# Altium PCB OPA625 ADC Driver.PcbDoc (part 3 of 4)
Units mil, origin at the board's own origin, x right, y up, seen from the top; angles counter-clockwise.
Board outline 4590 x 3930 mil, 4 copper layers (Layer 1 - Top Layer, Layer 2 - GND, Layer 3 - PWR, Layer 4 - Bottom Layer), stack 59.034 mil thick; 428 components, 236 nets, 1203 pads, 546 vias.
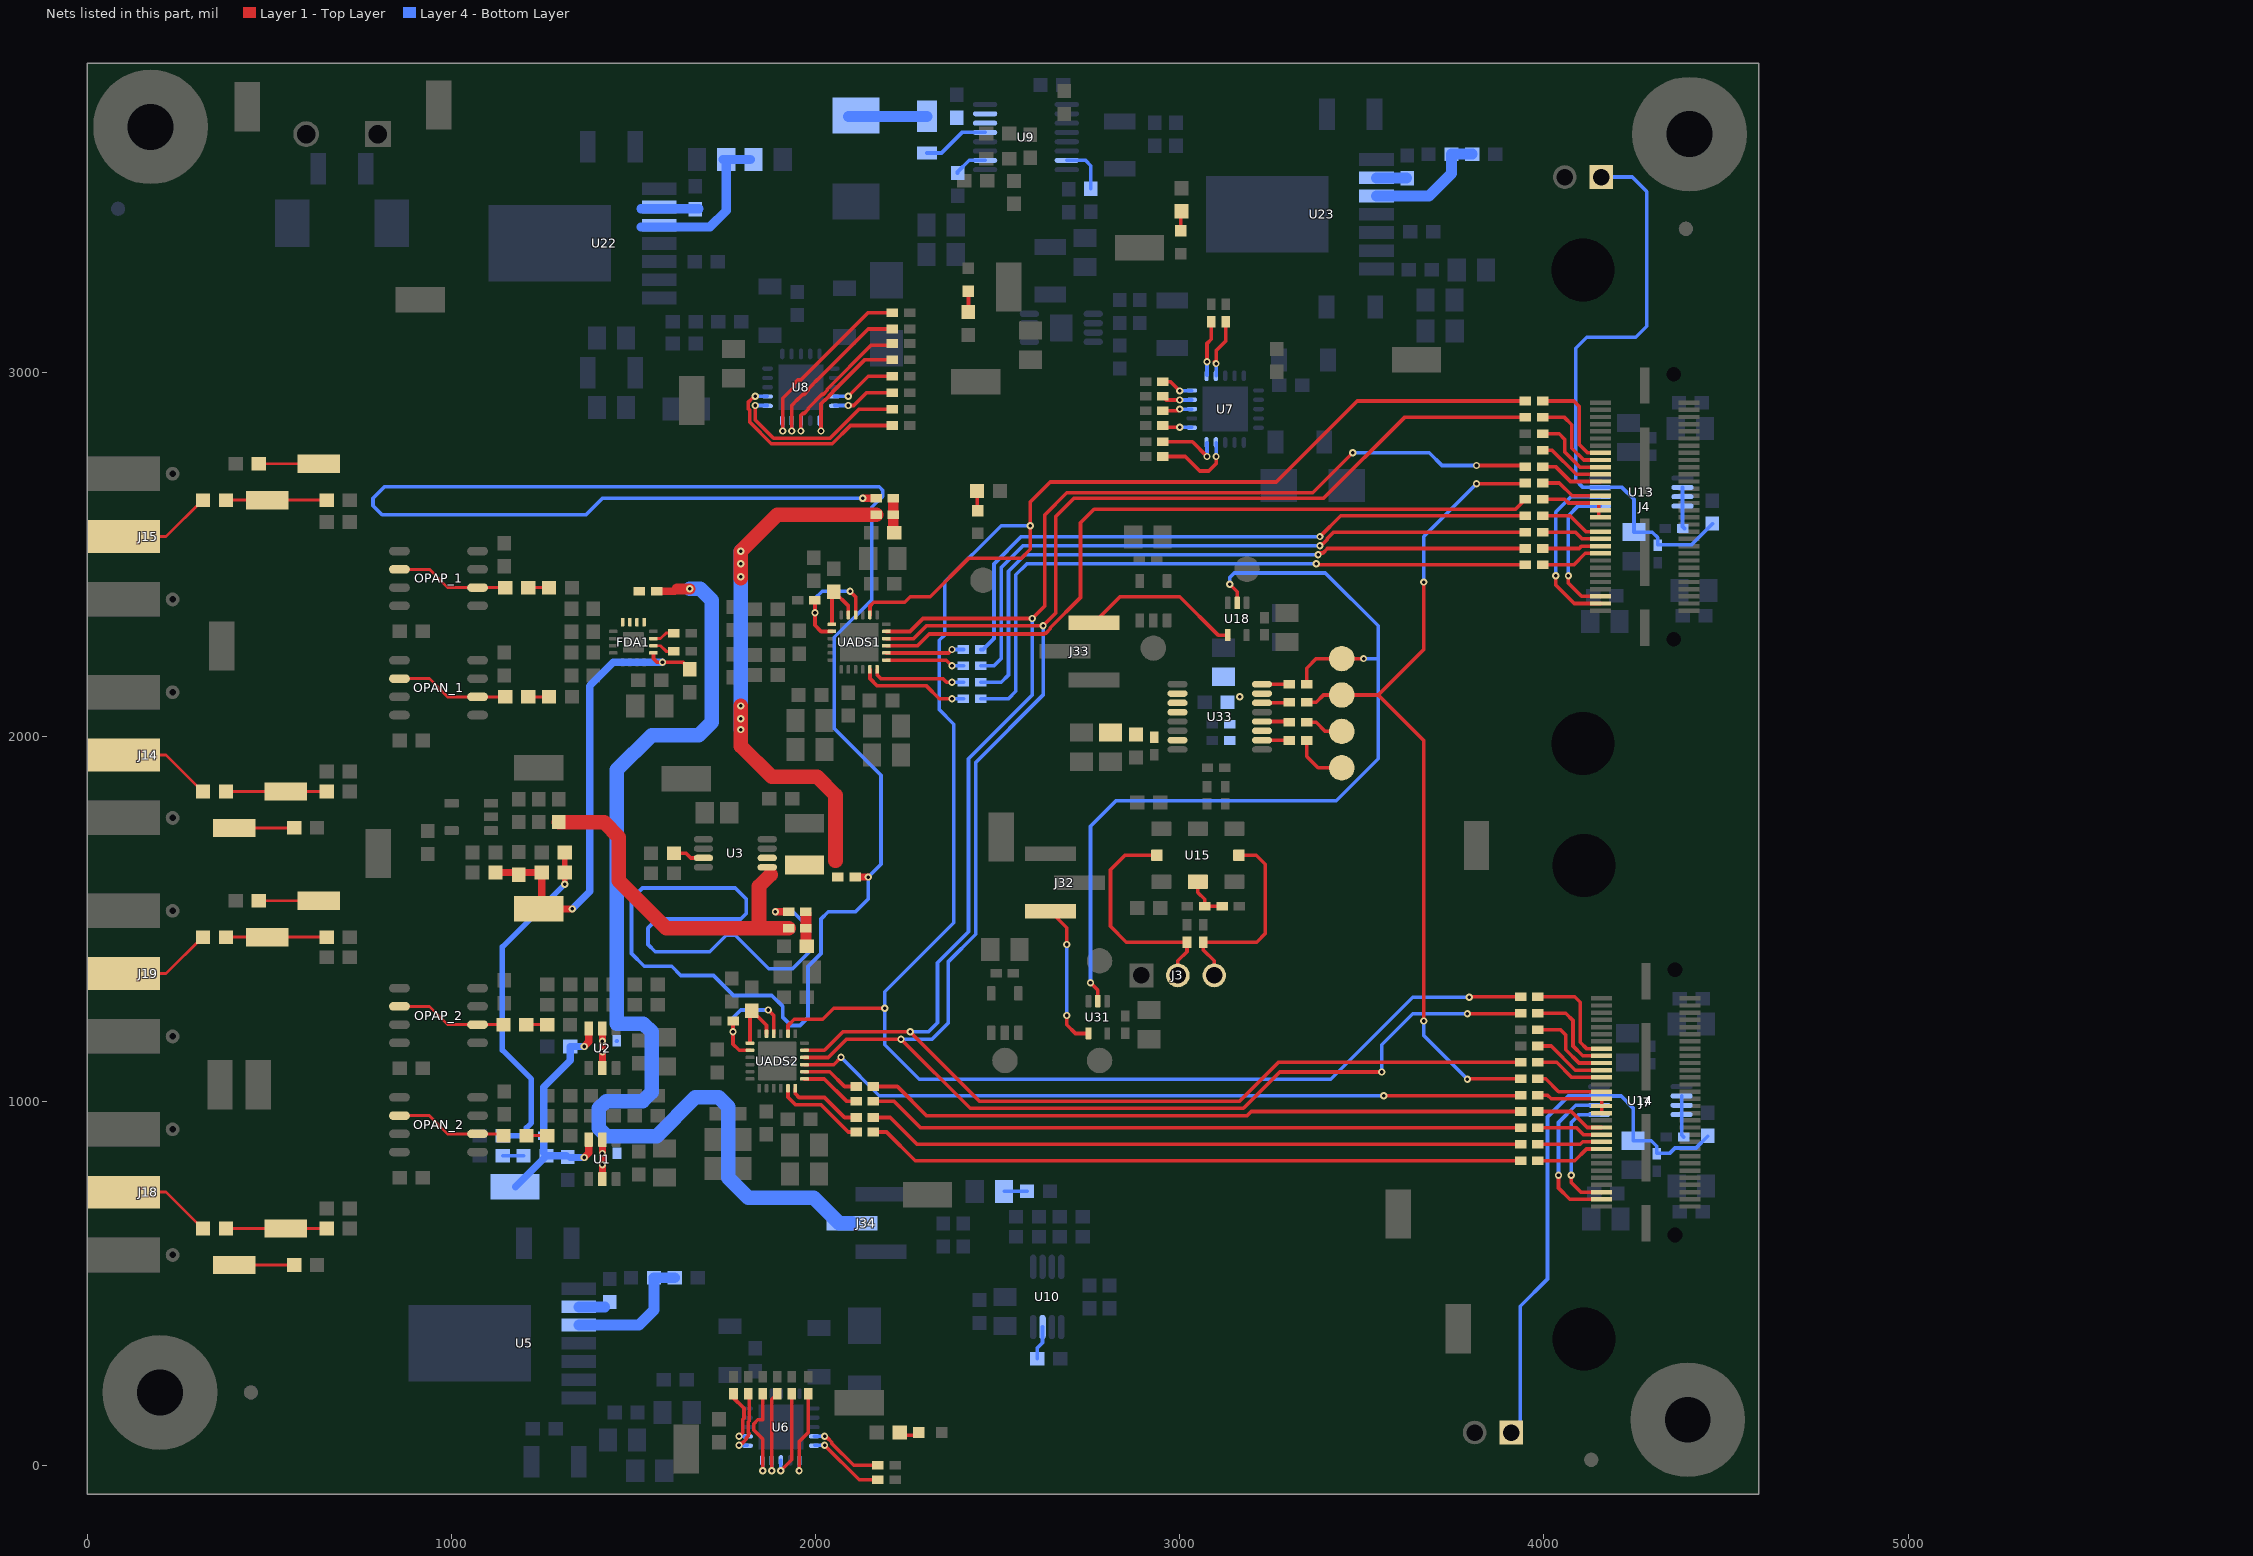
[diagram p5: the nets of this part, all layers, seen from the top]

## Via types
v1: diameter 20, hole 10, Layer 1 - Top Layer to Layer 4 - Bottom Layer, tented both sides, 512 vias
v2: diameter 19.68, hole 7.87, Layer 1 - Top Layer to Layer 4 - Bottom Layer, tented both sides, 34 vias

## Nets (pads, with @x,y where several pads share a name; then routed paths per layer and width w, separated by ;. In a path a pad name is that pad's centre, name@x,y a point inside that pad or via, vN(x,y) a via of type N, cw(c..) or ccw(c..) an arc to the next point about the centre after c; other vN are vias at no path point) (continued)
NetD5_2: D5.2 U9.13 | length 182.9
  Layer 4 - Bottom Layer w10: D5.2@2306.17,3603.15 2345.97,3603.15 2402.51,3659.69 U9.13@2465.66,3659.69
NetD14_2: D14.2 R46.1 | length 47
  Layer 1 - Top Layer w10: R46.1@2235.75,82.56 D14.2@2282.76,82.56
NetD18_2: D18.2 R47.1 | length 52.7
  Layer 1 - Top Layer w10: D18.2@2444.11,2626.78 R47.1@2444.11,2677.37 ; R47.1@2444.9,2678.17 R47.1@2446.38,2676.69
NetD21_2: D21.2 R246.1 | length 52.1
  Layer 1 - Top Layer w10: D21.2@3003.32,3389.73 R246.1@3003.32,3441.82
NetD22_2: D22.2 R247.1 | length 47
  Layer 1 - Top Layer w10: R247.1@2420,3166.5 D22.2@2420,3213.5
NetFDA1_10: FDA1.10 R211.1 | length 62.5
  Layer 1 - Top Layer w8: FDA1.10@1555.12,2250.16 1574.84,2250.16 1590,2235 R211.1@1611.38,2235
NetFDA1_11: FDA1.11 R212.1 | length 62.5
  Layer 1 - Top Layer w8: FDA1.11@1555.12,2269.84 1574.84,2269.84 1590,2285 R212.1@1611.38,2285
NetFDA1_13: FDA1.13 FDA1.14 FDA1.15 FDA1.16 R248.1
NetJ4_16: J4.16 R65.2 | length 278.1
  Layer 1 - Top Layer w10: R65.2@3997.34,2922.18 4081.85,2922.18 4096.85,2907.18 4096.85,2802.67 4119.54,2779.99 J4.16@4155.35,2779.98
NetJ4_18: J4.18 R66.2 | length 244.9
  Layer 1 - Top Layer w10: R66.2@3996.7,2877.19 4056.85,2877.18 4076.85,2857.18 4076.85,2792.67 4109.24,2760.29 J4.18@4155.35,2760.28
NetJ4_20: J4.20 R67.2 | length 216.8
  Layer 1 - Top Layer w10: R67.2@3996.7,2832.19 4041.85,2832.18 4056.85,2817.18 4056.85,2782.67 4098.94,2740.59 J4.20@4155.35,2740.58
NetJ4_22: J4.22 R68.2 | length 186.1
  Layer 1 - Top Layer w10: R68.2@3996.7,2787.19 4022.35,2787.18 4088.64,2720.89 J4.22@4155.35,2720.88
NetJ4_24: J4.24 R69.2 | length 175.6
  Layer 1 - Top Layer w10: R69.2@3996.7,2742.19 4031.85,2742.18 4072.85,2701.19 J4.24@4155.35,2701.18
NetJ4_28: J4.28 R70.2 | length 173.3
  Layer 1 - Top Layer w10: R70.2@3996.7,2697.19 4042.34,2697.19 4077.74,2661.79 J4.28@4155.35,2661.78
NetJ4_30: J4.30 J4.32 J4.34 R71.2 | length 202.2
  Layer 1 - Top Layer w10: R71.2@3996.7,2652.19 4057.34,2652.19 4067.44,2642.09 J4.30@4150.35,2642.09 ; J4.34@4150.35,2602.69 J4.30@4150.35,2642.09 ; J4.30@4155.35,2642.08 J4.30@4150.35,2642.09
NetJ4_38: J4.38 R72.2 | length 176.8
  Layer 1 - Top Layer w10: R72.2@3996.7,2607.19 4071.85,2607.18 4115.75,2563.29 J4.38@4155.35,2563.28
NetJ4_40: J4.40 R73.2 | length 166.4
  Layer 1 - Top Layer w10: R73.2@3996.7,2562.19 4086.85,2562.18 4105.45,2543.59 J4.40@4155.35,2543.58
NetJ4_42: J4.42 R74.2 | length 161.4
  Layer 1 - Top Layer w10: R74.2@3996.7,2517.19 4096.85,2517.18 4103.56,2523.89 J4.42@4155.35,2523.88
NetJ4_44: J4.44 R75.2 | length 171.9
  Layer 1 - Top Layer w10: R75.2@3996.7,2472.19 4081.85,2472.18 4113.86,2504.19 J4.44@4155.35,2504.18
NetJ7_16: J7.16 R76.2 | length 303.2
  Layer 1 - Top Layer w10: R76.2@3978.62,1286.31 4085,1286.31 4100,1271.31 4100,1161.31 4117.19,1144.12 J7.16@4158.5,1144.12
NetJ7_18: J7.18 R77.2 | length 269.3
  Layer 1 - Top Layer w10: R77.2@3978.62,1241.31 4060,1241.31 4080,1221.31 4080,1151.31 4106.89,1124.42 J7.18@4158.5,1124.42
NetJ7_20: J7.20 R78.2 | length 241.2
  Layer 1 - Top Layer w10: R78.2@3978.62,1196.31 4045,1196.31 4060,1181.31 4060,1141.31 4096.59,1104.72 J7.20@4158.5,1104.72
NetJ7_22: J7.22 R79.2 | length 207.3
  Layer 1 - Top Layer w10: R79.2@3978.62,1151.31 4020,1151.31 4086.29,1085.02 J7.22@4158.5,1085.02
NetJ7_24: J7.24 R80.2 | length 196.9
  Layer 1 - Top Layer w10: R80.2@3978.62,1106.31 4035,1106.31 4075.99,1065.32 J7.24@4158.5,1065.32
NetJ7_28: J7.28 R81.2 | length 194.5
  Layer 1 - Top Layer w10: R81.2@3978.62,1061.31 4005,1061.31 4040.39,1025.92 J7.28@4158.5,1025.92
NetJ7_30: J7.30 J7.32 J7.34 R82.2 | length 223.5
  Layer 1 - Top Layer w10: R82.2@3978.62,1016.31 4010,1016.31 4020.09,1006.22 J7.30@4158.5,1006.22 J7.34@4158.5,966.82
NetJ7_38: J7.38 R83.2 | length 198.1
  Layer 1 - Top Layer w10: R83.2@3978.62,971.31 4075,971.31 4118.89,927.42 J7.38@4158.5,927.42
NetJ7_40: J7.40 R84.2 | length 187.6
  Layer 1 - Top Layer w10: R84.2@3978.62,926.31 4090,926.31 4108.59,907.72 J7.40@4158.5,907.72
NetJ7_42: J7.42 R85.2 | length 182.7
  Layer 1 - Top Layer w10: R85.2@3978.62,881.31 4100,881.31 4106.7,888.02 J7.42@4158.5,888.02
NetJ7_44: J7.44 R86.2 | length 193.1
  Layer 1 - Top Layer w10: R86.2@3978.62,836.31 4085,836.31 4117,868.32 J7.44@4158.5,868.32
NetJ13_1: J13.1 R270.1 | length 164.4
  Layer 1 - Top Layer w8: J13.1@404.13,1750 R270.1@568.5,1750
NetJ13_2: J13.2 R97.1 R219.2 | length 275.5
  Layer 1 - Top Layer w8: R219.2@381.5,1850 R97.1@656.95,1850
NetJ16_1: J16.1 R271.1 | length 164.4
  Layer 1 - Top Layer w8: R271.1@471.5,2750 J16.1@635.87,2750
NetJ16_2: J16.2 R98.1 R220.2 | length 262
  Layer 1 - Top Layer w8: R220.2@381.5,2650 R98.1@643.5,2650
NetJ17_1: J17.1 R1.1 | length 164.4
  Layer 1 - Top Layer w8: J17.1@404.13,550 R1.1@568.5,550
NetJ17_2: J17.2 R107.1 R221.2 | length 277
  Layer 1 - Top Layer w8: R221.2@381.5,650 J17.2@545.87,650 R107.1@658.5,650
NetJ20_1: J20.1 R2.1 | length 161.4
  Layer 1 - Top Layer w8: R2.1@474.43,1550 J20.1@635.87,1550
NetJ20_2: J20.2 R108.1 R222.2 | length 280.5
  Layer 1 - Top Layer w8: R222.2@381.5,1450 J20.2@494.13,1450 R108.1@658.5,1450 R108.1@661.95,1450
NetJ32_1: J32.1 U31.4 | length 399.9
  Layer 1 - Top Layer w10: J32.1@2645.04,1521.26 2690,1476.3 v1(2690,1430) ; v1(2690,1235) 2690,1209.42 2713.71,1185.71 U31.4@2749.62,1185.71
  Layer 4 - Bottom Layer w10: v1(2690,1235) v1(2690,1430)
NetJ33_1: J33.1 U18.4 | length 443.4
  Layer 1 - Top Layer w10: J33.1@2764.96,2313.74 2836.22,2385 3000,2385 3105.49,2279.51 U18.4@3132.22,2279.51 U18.4@3130.13,2277.42
NetL5_2: L5.2 R22.2 | length 62.8
  Layer 4 - Bottom Layer w10: L5.2@2517.91,752.23 R22.2@2580.75,752.23
NetOPAN_1_2: OPAN_1.2 OPAN_1.6 RDP1.1 | length 311.5
  Layer 1 - Top Layer w8: OPAN_1.2@857.71,2160 939.99,2160 989.99,2110 OPAN_1.6@1072.28,2110 RDP1.1@1148.5,2110
NetOPAN_2_2: OPAN_2.2 OPAN_2.6 RDP3.1 | length 301.5
  Layer 1 - Top Layer w8: OPAN_2.2@857.72,960 940,960 990,910 OPAN_2.6@1072.28,910 RDP3.1@1138.5,910
NetOPAP_1_2: OPAP_1.2 OPAP_1.6 RDN1.1 | length 311.5
  Layer 1 - Top Layer w8: OPAP_1.2@857.72,2460 940,2460 990,2410 OPAP_1.6@1072.28,2410 RDN1.1@1148.5,2410
NetOPAP_2_2: OPAP_2.2 OPAP_2.6 RDN3.1 | length 306.2
  Layer 1 - Top Layer w8: OPAP_2.2@857.72,1260 940,1260 990,1210 OPAP_2.6@1072.28,1210 RDN3.1@1143.19,1210
NetR3_2: R3.2 U3.3 | length 86.2
  Layer 1 - Top Layer w10: R3.2@1611.5,1680.41 1644.79,1680.41 1657.58,1667.62 U3.3@1692.4,1667.62
NetR8_2: R8.2 U8.4 | length 182
  Layer 1 - Top Layer w10: v1(2090,2935) 2145,2990 R8.2@2211.38,2990
  Layer 4 - Bottom Layer w10: U8.4@2052.13,2935 v1(2090,2935)
NetR9_2: R9.2 U8.5 | length 173.2
  Layer 1 - Top Layer w10: v1(2090,2910) 2105,2910 2140,2945 R9.2@2211.38,2945
  Layer 4 - Bottom Layer w10: U8.5@2052.72,2910 v1(2090,2910)
NetR10_2: R10.2 U8.6 | length 347
  Layer 1 - Top Layer w10: v1(2015,2840) 2015,2915 2025.16,2925.16 2026.6,2925.16 2047.01,2945.57 2047.01,2947.01 2135.98,3035.98 R10.2@2211.38,3035.98
  Layer 4 - Bottom Layer w10: v1(2015,2840) U8.6@2015,2864.65
NetR11_2: R11.2 U8.8 | length 405.9
  Layer 1 - Top Layer w10: v1(1960,2840) 1960,2882.77 1965.23,2887.99 1968.22,2887.99 1979.84,2899.62 1979.84,2902.61 2017.39,2940.16 2020.38,2940.16 2032.01,2951.78 2032.01,2954.77 2152.59,3075.35 R11.2@2211.38,3075.35
  Layer 4 - Bottom Layer w10: v1(1960,2840) U8.8@1960,2868.46
NetR12_2: R12.2 U8.9 | length 463.7
  Layer 1 - Top Layer w10: 1934.41,2868.46 1934.41,2909.41 1940.16,2915.16 1940.16,2916.05 1951.78,2927.68 1952.68,2927.68 1965.16,2940.16 1968.22,2940.16 1979.84,2951.78 1979.84,2954.84 1992.32,2967.32 1992.32,2968.22 2003.95,2979.84 2004.84,2979.84 2145,3120 R12.2@2211.38,3120 ; v1(1935,2840) 1935,2867.87
  Layer 4 - Bottom Layer w10: v1(1935,2840) U8.9@1935,2867.87
NetR13_2: R13.2 U8.10 | length 520.7
  Layer 1 - Top Layer w10: v1(1910,2840) 1910,2930 1940.16,2960.16 1940.16,2968.22 1951.78,2979.84 1959.84,2979.84 2145,3165 R13.2@2211.38,3165
  Layer 4 - Bottom Layer w10: v1(1910,2840) U8.10@1910,2867.28
NetR14_2: R14.2 U8.11 | length 502.5
  Layer 1 - Top Layer w10: v1(1835,2910) 1835,2870 1885,2820 2040,2820 2120,2900 R14.2@2211.38,2900
  Layer 4 - Bottom Layer w10: v1(1835,2910) U8.11@1867.28,2910
NetR15_2: R15.2 U8.12 | length 545.7
  Layer 1 - Top Layer w10: v1@1830,2930 1826.72,2930 1815,2918.28 1815,2901.72 1820,2896.72 1820,2863.79 1878.79,2805 2046.21,2805 2096.21,2855 R15.2@2211.38,2855
  Layer 4 - Bottom Layer w10: v1(1835,2935) U8.12@1867.87,2935
NetR17_2: R17.2 U7.4 | length 229.1
  Layer 1 - Top Layer w10: R17.2@2953.62,2770 3015,2770 3055,2730 3080,2730 3100,2750 v1(3100,2770)
  Layer 4 - Bottom Layer w10: v1(3100,2770) U7.4@3100,2807.87
NetR18_2: R18.2 U7.5 | length 175.2
  Layer 1 - Top Layer w10: R18.2@2953.62,2810 3035,2810 v1(3075,2770)
  Layer 4 - Bottom Layer w10: v1(3075,2770) U7.5@3075,2807.28
NetR19_2: R19.2 U7.6 | length 80.7
  Layer 1 - Top Layer w10: R19.2@2953.62,2855 2958.62,2850 v1(3000,2850)
  Layer 4 - Bottom Layer w10: v1(3000,2850) U7.6@3032.28,2850
NetR20_2: R20.2 U7.8 | length 81.9
  Layer 1 - Top Layer w10: R20.2@2953.62,2895 2995,2895 v1(3000,2900)
  Layer 4 - Bottom Layer w10: v1(3000,2900) U7.8@3033.46,2900
NetR21_2: R21.2 U10.3 | length 93.4
  Layer 4 - Bottom Layer w10: R21.2@2608.77,292.23 2608.77,322 2623.54,336.76 U10.3@2623.54,379.55
NetR24_2: R24.2 U7.9 | length 83.4
  Layer 1 - Top Layer w10: R24.2@2953.62,2935 2963.62,2925 v1(3000,2925)
  Layer 4 - Bottom Layer w10: v1(3000,2925) U7.9@3032.87,2925
NetR25_2: R25.2 U7.10 | length 89
  Layer 1 - Top Layer w10: R25.2@2953.62,2975 2975,2975 v1(3000,2950)
  Layer 4 - Bottom Layer w10: v1(3000,2950) U7.10@3032.28,2950
NetR26_2: R26.2 U7.11 | length 152.6
  Layer 1 - Top Layer w10: v1(3075,3030) 3075,3080 3086.81,3091.81 R26.2@3086.81,3140.43
  Layer 4 - Bottom Layer w10: U7.11@3075,2992.72 v1(3075,3030)
NetR27_2: R27.2 U7.12 | length 166.5
  Layer 1 - Top Layer w10: v1@3095,3030 v1(3100,3025) 3100,3060 3126.81,3086.81 R27.2@3126.81,3140.43
  Layer 4 - Bottom Layer w10: U7.12@3100,2992.13 v1(3100,3025)
NetR29_2: R29.2 U6.4 | length 209.3
  Layer 1 - Top Layer w10: v1(2025,80) 2030,75 2033.28,75 2045,63.28 2045,60 2105,0 R29.2@2171.38,0
  Layer 4 - Bottom Layer w10: U6.4@1997.13,80 v1(2025,80)
NetR30_2: R30.2 U6.5 | length 213
  Layer 1 - Top Layer w10: v1(2025,55) 2120,-40 R30.2@2171.38,-40
  Layer 4 - Bottom Layer w10: U6.5@1997.72,55 v1(2025,55)
NetR31_2: R31.2 U6.6 | length 249
  Layer 1 - Top Layer w10: v1(1955,-15) 1955,65 1980,90 R31.2@1980,196.38
  Layer 4 - Bottom Layer w10: v1(1955,-15) U6.6@1955,12.28
NetR32_2: R32.2 U6.8 | length 252.3
  Layer 1 - Top Layer w10: v1(1905,-15) 1935,15 R32.2@1935,196.38
  Layer 4 - Bottom Layer w10: v1(1905,-15) U6.8@1905,13.46
NetR33_2: R33.2 U6.9 | length 245.5
  Layer 1 - Top Layer w10: v1(1880,-15) 1880,181.38 R33.2@1895,196.38
  Layer 4 - Bottom Layer w10: v1(1880,-15) U6.9@1880,12.87
NetR34_2: R34.2 U6.10 | length 267
  Layer 1 - Top Layer w10: v1(1855,-15) 1855,71.94 1830.16,96.78 1830.16,113.22 1841.78,124.84 1855,124.84 R34.2@1855,196.38
  Layer 4 - Bottom Layer w10: v1(1855,-15) U6.10@1855,12.28
NetR35_2: R35.2 U6.11 | length 181.7
  Layer 1 - Top Layer w10: v1(1790,55) 1795,60 1798.28,60 1810,71.72 1810,75 1815,80 1815,83.79 1818.47,87.26 1815.16,90.57 1815.16,119.43 1818.62,122.9 1818.62,192.76 R35.2@1815,196.38
  Layer 4 - Bottom Layer w10: v1(1790,55) U6.11@1812.28,55
NetR36_2: R36.2 U6.12 | length 156.8
  Layer 1 - Top Layer w10: R36.2@1775,196.38 1775,185 1803.62,156.38 1803.62,129.11 1800.16,125.65 1800.16,90.16 1800,90 v1(1790,80)
  Layer 4 - Bottom Layer w10: v1(1790,80) U6.12@1812.87,80
NetR50_2: R50.2 U9.7 | length 135.6
  Layer 4 - Bottom Layer w10: U9.7@2690.07,3582.91 2741.6,3582.91 2756.17,3568.35 R50.2@2756.17,3504.84
NetR90_2: R90.2 R91.2 U15.2@3050,1602.17 | length 122.6
  Layer 1 - Top Layer w10: U15.2@3050,1602.17 3050,1573 3068.62,1554.38 R91.2@3068.62,1535 R90.2@3116.38,1535
NetR95_1: R95.1 U33.16 | length 75.4
  Layer 1 - Top Layer w10: U33.16@3226.14,2144.57 3300.95,2144.57 R95.1@3301.38,2145
NetR110_1: R110.1 R111.2 | length 57
  Layer 4 - Bottom Layer w10: R111.2@1141.5,850 R110.1@1198.5,850
NetR223_1: R223.1 UADS2.17 | length 251.1
  Layer 1 - Top Layer w10: UADS2.17@1924.53,1035.2 1924.53,1010.47 1945,990 2015,990 2090,915 R223.1@2111.38,915
NetR225_1: R225.1 UADS2.19 | length 166.8
  Layer 1 - Top Layer w10: UADS2.19@1969.8,1060.79 2024.21,1060.79 2085,1000 R225.1@2111.38,1000
NetR226_1: R226.1 UADS2.20 | length 158.3
  Layer 1 - Top Layer w10: UADS2.20@1969.8,1080.47 2039.53,1080.47 2080,1040 R226.1@2111.38,1040
NetR232_1: R232.1 UADS1.17 | length 298.2
  Layer 1 - Top Layer w10: UADS1.17@2149.53,2185.2 2149.53,2160.47 2170,2140 2305,2140 2340,2105 v1@2368.62,2105
  Layer 4 - Bottom Layer w10: v1(2375,2105) R232.1@2406.38,2105
NetR233_1: R233.1 UADS1.18 | length 260.2
  Layer 1 - Top Layer w10: UADS1.18@2169.21,2185.2 2169.21,2170.79 2180,2160 2350,2160 2360,2150 v1(2375,2150)
  Layer 4 - Bottom Layer w10: v1(2375,2150) R233.1@2406.38,2150
NetR234_1: R234.1 UADS1.19 | length 218.1
  Layer 1 - Top Layer w10: UADS1.19@2194.8,2210.79 2359.21,2210.79 v1(2375,2195)
  Layer 4 - Bottom Layer w10: v1(2375,2195) R234.1@2406.38,2195
NetR235_1: R235.1 UADS1.20 | length 215.5
  Layer 1 - Top Layer w10: UADS1.20@2194.8,2230.47 2365.47,2230.47 v1(2375,2240)
  Layer 4 - Bottom Layer w10: v1(2375,2240) R235.1@2406.38,2240
NetR240_1: R240.1 UADS2.18 | length 208.8
  Layer 1 - Top Layer w10: UADS2.18@1944.21,1035.2 1944.21,1020.79 1955,1010 2025,1010 2080,955 R240.1@2111.38,955
NetR250_1: R250.1 U1.2 U1.5 | length 108.3
  Layer 1 - Top Layer w20: U1.5@1415,785.87 v1(1415,825) v1(1415,856.38) U1.2@1415,894.13
NetR252_1: R252.1 U2.2 U2.5 | length 110
  Layer 1 - Top Layer w20: U2.5@1415,1090.87 v1(1415,1135) v1(1415,1164.68) ; v1@1415,1165 U2.2@1415,1199.13
  Layer 4 - Bottom Layer w10: R252.1@1453.52,1164.68 R252.1@1454.48,1165.64 R252.1@1455,1165.13
NetR256_1: R256.1 U33.14 | length 75.9
  Layer 1 - Top Layer w10: U33.14@3226.14,2093.39 3299.76,2093.39 R256.1@3301.38,2095
NetR257_1: R257.1 U33.12 | length 76.2
  Layer 1 - Top Layer w10: U33.12@3226.14,2042.2 3299.18,2042.2 R257.1@3301.38,2040
NetR258_2: R258.2 R259.2 R260.2 | length 91.2
  Layer 1 - Top Layer w30: R260.2@2213.62,2650 R259.2@2213.62,2610 2213.62,2562.87 R258.2@2216.5,2560
NetR261_2: R261.2 R262.1 R263.1 | length 87.1
  Layer 1 - Top Layer w30: R261.2@1973.62,1427.87 R263.1@1973.62,1515
NetR278_1: R278.1 U33.10 | length 75.7
  Layer 1 - Top Layer w10: U33.10@3226.14,1991.02 3300.36,1991.02 R278.1@3301.38,1990
NetR279_2: R279.2 U13.2 U13.3 U13.4 | length 115
  Layer 4 - Bottom Layer w10: U13.2@4380.53,2684.98 U13.3@4380.53,2659.39 U13.4@4380.53,2633.8 4380.53,2577.62 R279.2@4385.96,2572.19
NetR280_2: R280.2 U14.2 U14.3 U14.4 | length 115
  Layer 4 - Bottom Layer w10: U14.2@4378.18,1014.11 U14.3@4378.18,988.52 U14.4@4378.18,962.93 4378.18,906.75 R280.2@4383.61,901.32
NetR284_2: R284.2 UADS1.4 UADS1.8 | length 337.8
  Layer 1 - Top Layer w10: R284.2@1998.62,2375 v1(1998.62,2340.69) 1998.62,2306.38 2015.47,2289.53 UADS1.8@2045.2,2289.53 ; v1(2095,2400) 2110.16,2384.84 UADS1.4@2110.16,2334.8
  Layer 4 - Bottom Layer w10: v1(1998.62,2340.69) 1998.62,2380.28 2018.35,2400 v1(2095,2400)
NetR288_2: R288.2 UADS2.4 UADS2.8 | length 331.8
  Layer 1 - Top Layer w10: R288.2@1773.62,1220 v1(1773.62,1190.69) 1773.62,1156.38 1790.47,1139.53 UADS2.8@1820.2,1139.53 ; v1(1870,1250) 1885.16,1234.84 UADS2.4@1885.16,1184.8
  Layer 4 - Bottom Layer w10: v1(1773.62,1190.69) 1773.62,1228.62 1795,1250 v1(1870,1250)
NetRDN1_2: RDN1.2 RDN2.1 | length 57
  Layer 1 - Top Layer w8: RDN1.2@1211.5,2410 RDN2.1@1268.5,2410
NetRDN3_2: RDN3.2 RDN4.1 | length 57
  Layer 1 - Top Layer w8: RDN3.2@1206.18,1210 RDN4.1@1263.19,1210
NetRDP1_2: RDP1.2 RDP2.1 | length 57
  Layer 1 - Top Layer w8: RDP1.2@1211.5,2110 RDP2.1@1268.5,2110
NetRDP3_2: RDP3.2 RDP4.1 | length 57
  Layer 1 - Top Layer w8: RDP3.2@1206.5,905 RDP4.1@1263.5,905
NetRenb2_2: Renb2.2 Rent2.1 U23.3 | length 341.9
  Layer 4 - Bottom Layer w30: U23.3@3540.39,3485 3684.76,3485 3746.26,3546.5 Rent2.1@3746.26,3600 Renb2.2@3803.27,3600
NetRenb3_2: Renb3.2 Rent3.1 U5.3 | length 368.6
  Layer 4 - Bottom Layer w30: U5.3@1350.63,385 1515,385 1556.5,426.5 Rent3.1@1556.5,515 Renb3.2@1613.5,515
NetRenb_2: Renb.2 Rent.1 U22.3 | length 468
  Layer 4 - Bottom Layer w25: 1520.63,3400 1710,3400 1755,3445 Rent.1@1755,3585 ; Rent.1@1746,3585 Renb.2@1821,3585
NetRon2_1: Ron2.1 U23.2 | length 82.9
  Layer 4 - Bottom Layer w30: U23.2@3540.39,3535 Ron2.1@3623.27,3535
NetRon3_1: Ron3.1 U5.2 | length 70.9
  Layer 4 - Bottom Layer w30: U5.2@1350.63,435 Ron3.1@1421.5,435
NetRon_1: Ron.1 U22.2 | length 159.4
  Layer 4 - Bottom Layer w25: 1520.63,3450 Ron.1@1680,3450
NISO_SCL_DIF: J4.58 U13.6 | length 483.4
  Layer 1 - Top Layer w10: v1(4032.34,2442.19) 4032.34,2417.19 4083.25,2366.28 J4.58@4155.35,2366.28
  Layer 4 - Bottom Layer w10: v1(4032.34,2442.19) 4032.34,2617.19 4074.55,2659.39 U13.6@4154.15,2659.39
NISO_SCL_SE: J7.58 U14.6 | length 442.7
  Layer 1 - Top Layer w10: v1(4039.99,796.32) 4039.99,761.32 4070.89,730.42 J7.58@4158.5,730.42
  Layer 4 - Bottom Layer w10: v1(4039.99,796.32) 4039.99,941.32 4087.2,988.52 U14.6@4151.8,988.52
NISO_SDA_DIF: J4.56 U13.5 | length 385.8
  Layer 1 - Top Layer w10: v1(4067.34,2442.19) 4067.34,2422.19 4103.55,2385.98 J4.56@4155.35,2385.98
  Layer 4 - Bottom Layer w10: v1(4067.34,2442.19) 4067.34,2607.19 4093.96,2633.8 U13.5@4154.15,2633.8
NISO_SDA_SE: J7.56 U14.5 | length 345.1
  Layer 1 - Top Layer w10: v1(4074.99,796.32) 4074.99,776.32 4101.19,750.12 J7.56@4158.5,750.12
  Layer 4 - Bottom Layer w10: v1(4074.99,796.32) 4074.99,941.32 4096.61,962.93 U14.5@4151.8,962.93
PRE: C40.1 D5.1 L1.1 U9.14 U9.15 | length 215
  Layer 4 - Bottom Layer w30: L1.1@2091.17,3703.35 D5.1@2306.17,3703.54
REFBUF_DIF: C322.1 UADS1.5 UADS1.7 | length 165
  Layer 1 - Top Layer w10: UADS1.7@2045.2,2310 C322.1@2045.2,2393.7 ; C322.1@2050,2398.5 2051.5,2398.5 2090.47,2359.53 UADS1.5@2090.47,2334.8
REFBUF_SE: C323.1 UADS2.5 UADS2.7 | length 171
  Layer 1 - Top Layer w10: UADS2.7@1820.2,1160 1820.2,1243.7 C323.1@1825,1248.5 1865.47,1208.03 UADS2.5@1865.47,1184.8
RVS_DIF: R71.1 UADS1.21 | length 2043.2
  Layer 1 - Top Layer w10: UADS1.21@2194.8,2250.16 2280.16,2250.16 2312.58,2282.58 2627.58,2282.58 2630,2285 2633.28,2285 2645,2296.72 2645,2300 2727.81,2382.81 2727.81,2587.81 2765,2625 3922.27,2625 R71.1@3949.45,2652.19
RVS_SE: R82.1 UADS2.21 | length 2017
  Layer 1 - Top Layer w10: UADS2.21@1969.8,1100.16 2050.16,1100.16 v1(2070,1120) ; v1(3560,1015) R82.1@3935.05,1015
  Layer 4 - Bottom Layer w10: v1(2070,1120) 2175,1015 v1(3560,1015)
SCL: J3.3 R89.1 U15.8 | length 556.1
  Layer 1 - Top Layer w10: J3.3@3095,1345 3095,1385 3065,1415 R89.1@3065,1436.38 3211.38,1436.38 3235,1460 3235,1650 3210,1675 U15.8@3162.8,1675
SCLK: R69.1 R80.1 UADS1.23 UADS2.23 | length 5533.2
  Layer 1 - Top Layer w10: UADS2.23@1969.8,1139.53 2024.53,1139.53 2075,1190 v1(2260,1190) 2450,1000 3165,1000 3271.32,1106.32 R80.1@3936.37,1106.32 ; UADS1.23@2194.8,2289.53 2259.53,2289.53 2295,2325 v1(2595,2325) 2630,2360 2630,2610 2690,2670 3365,2670 v1(3475,2780) ; v1(3815,2745) 3946.64,2745 R69.1@3949.45,2742.19
  Layer 4 - Bottom Layer w10: v1(2260,1190) 2310,1190 2335,1215 2335,1380 2420,1465 2420,1940 2595,2115 v1(2595,2325) ; v1(3475,2780) 3685,2780 3720,2745 v1(3815,2745)
SDA: J3.2 R88.1 U15.7 | length 628.6
  Layer 1 - Top Layer w10: U15.7@2937.2,1675 2850,1675 2810,1635 2810,1480 2853.62,1436.38 R88.1@3020,1436.38 3020,1410 2995,1385 J3.2@2995,1345
SDI: R66.1 R77.1 UADS1.22 UADS2.22 | length 5714.1
  Layer 1 - Top Layer w10: UADS2.22@1969.8,1119.84 2034.84,1119.84 2085,1170 v1(2235,1170) 2425,980 3175,980 3275,1080 v1(3555,1080) ; UADS1.22@2194.8,2269.84 2269.84,2269.84 2305,2305 v1(2625,2305) 2660,2340 2660,2605 2710,2655 3395,2655 3617.19,2877.19 R66.1@3949.45,2877.19 ; v1(3790,1240) R77.1@3935.05,1240
  Layer 4 - Bottom Layer w10: v1(2235,1170) 2320,1170 2365,1215 2365,1383.44 2439.83,1458.27 2439.83,1929.83 2625,2115 2625,2295 ; v1(3555,1080) 3555,1155 3640,1240 v1(3790,1240)
SDO0_DIF: R72.1 R235.2 | length 1773
  Layer 1 - Top Layer w10: v1(3385,2550) 3442.19,2607.19 R72.1@3949.45,2607.19
  Layer 4 - Bottom Layer w10: R235.2@2453.62,2240 2460,2240 2490,2270 2490,2475 2565,2550 v1(3385,2550) v1@3390,2550
SDO0_SE: R83.1 R226.2 | length 1815.4
  Layer 1 - Top Layer w10: R226.2@2158.8,1040 2225,1040 2305,960 3185,960 3196.32,971.32 R83.1@3936.37,971.32
SDO1_DIF: R73.1 R234.2 | length 1796.3
  Layer 1 - Top Layer w10: v1(3385,2525) 3390,2530 3393.28,2530 3405,2541.72 3405,2545 3422.19,2562.19 R73.1@3949.45,2562.19
  Layer 4 - Bottom Layer w10: R234.2@2453.62,2195 2490,2195 2510,2215 2510,2465 2570,2525 v1(3385,2525)
SDO1_SE: R84.1 R225.2 | length 1808.3
  Layer 1 - Top Layer w10: R225.2@2158.62,1000 2215,1000 2288.68,926.32 R84.1@3936.37,926.32
SDO2_DIF: R74.1 R233.2 | length 1815.1
  Layer 1 - Top Layer w10: v1(3380,2500) 3385,2505 3393.28,2505 3405,2516.72 3405,2517.19 R74.1@3949.45,2517.19
  Layer 4 - Bottom Layer w10: R233.2@2453.62,2150 2510,2150 2530,2170 2530,2455 2575,2500 v1(3380,2500)
SDO2_SE: R85.1 R240.2 | length 1808.3
  Layer 1 - Top Layer w10: R240.2@2158.62,955 2205,955 2278.68,881.32 R85.1@3936.37,881.32
SDO3_DIF: R75.1 R232.2 | length 1837.7
  Layer 1 - Top Layer w10: v1(3375,2475) 3377.81,2472.19 R75.1@3949.45,2472.19
  Layer 4 - Bottom Layer w10: R232.2@2453.62,2105 2530,2105 2550,2125 2550,2445 2580,2475 v1(3375,2475)
SDO3_SE: R86.1 R223.2 | length 1810.3
  Layer 1 - Top Layer w10: R223.2@2158.62,915 2195,915 2273.68,836.32 R86.1@3936.37,836.32
SRESETN: R65.1 R76.1 UADS1.2 UADS2.2 | length 5990
  Layer 1 - Top Layer w10: UADS2.2@1924.53,1184.8 1924.53,1207.45 1942.07,1225 2020,1225 2050,1255 v1(2190,1255) ; UADS1.2@2149.53,2334.8 2149.53,2359.53 2160,2370 2245,2370 2260,2385 2315,2385 2420,2490 2565,2490 2590,2515 v1(2590,2580) 2590,2645 2645,2700 3265,2700 3487.19,2922.19 R65.1@3949.45,2922.19 ; v1@3796.32,1286.32 R76.1@3936.37,1286.32
  Layer 4 - Bottom Layer w10: v1(2590,2580) 2510,2580 2355,2425 2355,2280 2340,2265 2340,2075 2380,2035 2380,1490 2190,1300 v1(2190,1255) 2190,1155 2285,1060 3415,1060 3640,1285 v1(3795,1285)
SS: C34.1 U9.10 | length 91.3
  Layer 4 - Bottom Layer w10: C34.1@2390.15,3548.39 2390.15,3550.84 2422.22,3582.91 U9.10@2465.66,3582.91
SYSCLK0: R95.2 TP16.1 U18.2 U31.2 | length 2522.1
  Layer 1 - Top Layer w10: v1(2755,1325) 2775.21,1304.79 U31.2@2775.21,1274.29 ; v1(3137.6,2418.8) 3157.81,2398.59 U18.2@3157.81,2368.09 ; R95.2@3348.63,2145 3348.63,2188.63 3375,2215 TP16.1@3445,2215 v1(3505,2215)
  Layer 4 - Bottom Layer w10: v1(2755,1325) 2755,1755 2825,1825 3430,1825 3545,1940 3545,2215 ; v1(3137.6,2418.8) 3137.6,2437.6 3150,2450 3400,2450 3545,2305 3545,2215 ; v1(3505,2215) 3545,2215
SYSCLK1: R70.1 R81.1 R256.2 TP31.1 | length 2332.2
  Layer 1 - Top Layer w10: R256.2@3348.63,2095 3375,2095 3394.99,2115 TP31.1@3445,2115 3545,2115 ; v1(3670,1220) 3670,1990 3545,2115 ; v1(3670,2425) 3670,2240 3545,2115 ; v1(3790,1060) 3791.32,1061.32 R81.1@3936.37,1061.32 ; v1(3815,2695) R70.1@3947.27,2695
  Layer 4 - Bottom Layer w10: v1(3670,1220) 3670,1180 v1(3790,1060) ; v1(3670,2425) 3670,2550 v1(3815,2695)
SYSCLK2: R257.2 TP32.1 | length 106.7
  Layer 1 - Top Layer w10: R257.2@3348.63,2040 3375,2040 3400,2015 TP32.1@3445,2015
SYSCLK3: R278.2 TP33.1 | length 153
  Layer 1 - Top Layer w10: R278.2@3348.63,1990 3348.63,1946.37 3380,1915 TP33.1@3445,1915
V_CM: C84.1 FDA1.9 R214.1 R215.2 R216.2 TP29.1 | length 1301
  Layer 1 - Top Layer w10: FDA1.9@1555.12,2229 1555.12,2214.88 1565,2205 v1(1580,2205) 1636.5,2205 C84.1@1646.5,2195
  Layer 1 - Top Layer w20: R216.2@1121.5,1627.63 1178.5,1627.63 R215.2@1185,1621.13 1191.5,1627.63 R214.1@1248.5,1627.63 1248.5,1536.13 TP29.1@1240,1527.63 v1(1332.37,1527.63)
  Layer 4 - Bottom Layer w20: v1(1332.37,1527.63) 1380,1575.26 1380,2140 1445,2205 v1(1580,2205)
V_CM_OPA: C108.1 C318.1 R213.1 R214.2 | length 952.3
  Layer 1 - Top Layer w15: v1(1311.5,1595) R214.2@1311.5,1627.63 C318.1@1311.5,1682.63
  Layer 4 - Bottom Layer w15: C108.1@1141.5,905 R213.1@1206.38,905 1206.38,926.38 1220,940 1220,1060 1140,1140 1140,1423.5 v1(1311.5,1595)
V_REF_OPA0: C109.1 C115.1 R110.2 R213.2 TP30.1 U1.3 U2.3 | length 700.8
  Layer 1 - Top Layer w20: v1(1365,845) 1377.6,857.6 U1.3@1377.6,894.13 ; v1(1365,1150) 1377.6,1162.6 U2.3@1377.6,1199.13
  Layer 4 - Bottom Layer w10: TP30.1@1175,765 TP30.1@1176.5,765 ; R110.2@1253.62,857.87 R110.2@1261.5,850 ; C109.1@1316.5,850 C109.1@1320,846.5
  Layer 4 - Bottom Layer w20: TP30.1@1176.5,765 R110.2@1261.5,850 C109.1@1316.5,850 ; R110.2@1253.62,857.87 R213.2@1253.62,905 1253.62,1038.62 1326.5,1111.5 C115.1@1326.5,1150 v1(1365,1150) ; C109.1@1326.5,845 v1(1365,845)
VDD: C339.1 C340.1 L10.1 U33.2 U33.3 U33.4 U33.7
VDDO: C348.1 C349.1 C350.1 L12.1 U33.11 U33.15
  other v1: 3165,2110
VEE: J34.2 R248.2 R250.2 R252.2 | length 3007
  Layer 1 - Top Layer w20: R248.2@1563.62,2400 1613.5,2400 1620,2406.5
  Layer 1 - Top Layer w30: 1620,2406.5 v1(1655,2406.5)
  Layer 4 - Bottom Layer w40: v1(1655,2406.5) 1683.5,2406.5 1715,2375 1715,2040 1680,2005 1550,2005 1454.48,1909.48 R252.2@1454.48,1212.89 1527.11,1212.89 1550,1190 1550,1025 1525,1000 1425,1000 1405,980 1405,925 1426.38,903.62 R250.2@1455,903.62 1563.62,903.62 1670,1010 1735,1010 1760,985 1760,790 1815,735 1995,735 2065,665 J34.2@2100.04,665
VIN+_1: J15.1 R220.1 | length 258.4
  Layer 1 - Top Layer w8: J15.1@100,2550 217,2550 R220.1@317,2650
VIN+_2: J19.1 R222.1 | length 259.9
  Layer 1 - Top Layer w8: J19.1@100,1350 217,1350 317,1450 R222.1@318.5,1450
VIN-_1: J14.1 R219.1 | length 258.4
  Layer 1 - Top Layer w8: J14.1@100,1950 217,1950 R219.1@317,1850
VIN-_2: J18.1 R221.1 | length 258.4
  Layer 1 - Top Layer w8: J18.1@100,750 217,750 R221.1@317,650
VREF: C5.1 R218.2 R255.2 R259.1 R262.2 U3.5 U3.6 | length 2565.4
  Layer 1 - Top Layer w20: R218.2@1295,1766.13 R218.2@1295.66,1765.47
  Layer 1 - Top Layer w40: R218.2@1295.66,1765.47 1419.53,1765.47 1460,1725 1460,1605 1590,1475 1845,1475 ; v1(1795,2085) v1(1795,2050) v1(1795,2020) 1795,1975 1880,1890 2005,1890 2055,1840 2055,1660 ; v1@1795,2435 v1(1795,2440) v1(1795,2475) v1(1795,2510) 1895,2610 R259.1@2166.38,2610 ; 1876.5,1621.41 1845,1589.91 1845,1475 ; R262.2@1926.38,1475 1845,1475
  Layer 4 - Bottom Layer w40: v1(1795,2020) v1(1795,2050) v1(1795,2085) v1(1795,2440) v1(1795,2475) v1(1795,2510)
VREF1: R255.1 R260.1 R263.2 | length 6760.1
  Layer 1 - Top Layer w20: v1(1890,1520) R263.2@1926.38,1520 ; R255.1@2108.62,1615.41 2109.03,1615 v1(2145,1615) ; v1(2130,2655) R260.1@2166.38,2655
  Layer 4 - Bottom Layer w10: v1(1890,1520) 1938.19,1520 1981.05,1477.14 1981.05,1407.51 1937.05,1363.5 1871.5,1363.5 1780,1455 1755,1455 1710,1410 1560,1410 1540,1430 1540,1475 1565,1500 1795,1500 1810,1515 1810,1555 1780,1585 1525,1585 1495,1555 1495,1405 1530,1370 1605,1370 1630,1345 1720,1345 1775,1290 1880,1290 1910.57,1259.43 1910.57,1229.43 1932.55,1207.45 1957.45,1207.45 1979.45,1229.45 1979.45,1369.68 2015,1405.24 2015,1500 2035,1520 2110,1520 2145,1555 v1(2145,1615) 2180,1650 2180,1894.64 2051.85,2022.79 2051.85,2273.54 2155,2376.69 2155,2565 2154.84,2565 2154.84,2630.16 2185,2660.31 2185,2676.65 2175,2686.65 816.65,2686.65 785,2655 785,2635 810,2610 1370,2610 1415,2655 v1(2130,2655)
WP1_0: C54.2 C262.1 J5.1 R64.1 U13.7 | length 1632.6
  Layer 4 - Bottom Layer w10: J5.1@4157.34,3537.19 4242.34,3537.19 4282.34,3497.19 4282.34,3127.19 4252.34,3097.19 4117.34,3097.19 4087.34,3067.19 4087.34,2704.98 4107.34,2684.98 U13.7@4154.15,2684.98 4214.55,2684.98 4247.34,2652.19 C262.1@4247.34,2562.19 4297.34,2562.19 4312.35,2547.18 4312.35,2527.19 4405.13,2527.19 R64.1@4462.99,2585.04 ; R64.1@4462.34,2584.4 R64.1@4462.34,2585.69
WP1_1: C56.2 C261.1 J6.1 R87.1 U14.7 | length 1521
  Layer 4 - Bottom Layer w10: J6.1@3910,90 3934.99,114.99 3934.99,436.32 4009.99,511.32 4009.99,956.32 4067.79,1014.11 U14.7@4151.8,1014.11 4212.2,1014.11 4244.99,981.32 C261.1@4244.99,891.32 4294.99,891.32 4310,876.31 4310,856.32 4344.99,856.32 4359.99,871.32 4417.78,871.32 R87.1@4450,903.53
pads on no net: FID1.1 FID2.1 FID3.1 FID4.1 FID5.1 FID6.1 H1.1 H2.1 H3.1 H4.1 H9. H11. H13. H15. J4.2 J4.3 J4.4 J4.5 J4.6 J4.7 J4.8 J4.9 J4.10 J4.11 J4.12 J4.13 J4.14 J4.15 J4.17 J4.19 J4.21 J4.23 J4.25 J4.26 J4.27 J4.29 J4.31 J4.33 J4.35 J4.36 J4.37 J4.39 J4.41 J4.43 J4.45 J4.46 J4.47 J4.48 J4.49 J4.51 J4.52 J4.53 J4.54 J4.55 J4.57 J4.MH1 J4.MH2 J7.2 J7.3 J7.4 J7.5 J7.6 J7.7 J7.8 J7.9 J7.10 J7.11 J7.12 J7.13 J7.14 J7.15 J7.17 J7.19 J7.21 J7.23 J7.25 J7.26 J7.27 J7.29 J7.31 J7.33 J7.35 J7.36 J7.37 J7.39 J7.41 J7.43 J7.45 J7.46 J7.47 J7.48 J7.49 J7.51 J7.52 J7.53 J7.54 J7.55 J7.57 J7.MH1 J7.MH2 OPAN_1.1 OPAN_1.5 OPAN_1.8 OPAN_2.1 OPAN_2.5 OPAN_2.8 OPAP_1.1 OPAP_1.5 OPAP_1.8 OPAP_2.1 OPAP_2.5 OPAP_2.8 U9.2 U9.4 U11.3 U11.7 U15.1@2934.25,1602.17 U15.1@2965.75,1602.17 U15.2@3034.25,1602.17 U15.2@3065.75,1602.17 U15.3@3134.25,1602.17 U15.3@3165.75,1602.17 U15.4@3134.25,1747.83 U15.4@3165.75,1747.83 U15.5@3034.25,1747.83 U15.5@3065.75,1747.83 U15.6@2934.25,1747.83 U15.6@2965.75,1747.83 U19.1 U32.1 U33.8 UADS1.6 UADS2.6
copper on no net: | length 104.8
  Layer 4 - Bottom Layer w20: 810.24,1135 813.62,1135 v1(915,1135)

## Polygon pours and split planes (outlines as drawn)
3.3V on Layer 3 - PWR "Layer 3 - PWR - 3.3V" (solid, remove dead copper, pour order 14): 1498.93,626.07 2120,626.07 2120,670 2495,670 2495,805 2120,805 2120,1247.13 2416.46,1543.59 2416.46,2053.25 2416.46,2405 2648.23,2636.77 3250,2636.77 3588.23,2975 3735,2975 3892.51,2975 3892.51,3477.49 3982.52,3570 4000,3570 4560,3570 4560,1895 4560,1830 4560,-45 2170,-45
-18V on Layer 3 - PWR "Layer 3 - PWR - -18V" (solid, remove dead copper, pour order 12): 1413.27,1816.73 1421.7,2685 1230,2685 1230,2425 780,2425 780,2260 1230,2260 1230,2120 1180,2120 630,2120 570,2060 570,1315 1250,1315 1250,1286.02 1153.98,1190 800,1190 800,1065 995,1065 1230,1065 1230,930 415,930 365,880 365,730 400,695 1472.21,695 1472.21,1447.27 1421.7,1497.78 1421.7,1510 1421.7,1632.55 1379.63,1674.63 915.37,1674.63 875,1715 875,1765 933.27,1816.73
+18V on Layer 3 - PWR "Layer 3 - PWR - +18V" (solid, remove dead copper, pour order 10): 1203.02,2675 1203.02,2438.54 760,2438.54 760,2250 1203.02,2250 1203.02,2145 620,2145 545,2070 545,1290 1225,1290 1140,1205 1051.69,1205 770,1205 770,1055 1215,1055 1215,950 375,950 285,1040 285,2590 370,2675
5V on Layer 3 - PWR "Layer 3 - PWR - 5V" (solid, remove dead copper, pour order 8): 2165,2165 2165,2240 2165,2340 2200.85,2375.85 2220,2395 2220,2520 2265,2565 1435,2565 1435,2347.53 1435,1845 1380,1790 935,1790 905,1760 905,1755 905,1731.31 935,1701.31 1380,1701.31 1435,1646.31 1435,1640 1435,1512.67 1487.8,1459.87 1487.8,705 1565,705 1783.09,705 1910,705 1970,705 2030,765 2030,978.54 1935,978.54 1935,1012.68 1935,1171.64 1935,1190 1985,1240 2204.87,1459.87 2320,1575 2320,2010
GND on Layer 2 - GND "Layer 2 - GND - GND" (solid, remove dead copper, pour order 6): 20,2845 785,2845 825,2805 825,2735 2345,2735 2345,2450 2205.85,2310.85 2205.85,2219.15 2390,2035 2390,1540 2015,1165 1985,1165 1985,1045 2111.38,1045 2111.38,995 2111.38,640 825,640 825,525 780,480 20,480 20,-70.01 4575,-69.95 4575,3835 20,3835
AGND on Layer 2 - GND "Layer 2 - GND - AGND" (solid, remove dead copper, pour order 4): 215,525 765,525 780,540 780,660 805,685 2055,685 2055,990 1945.71,990 1945.71,1175.71 2340,1570 2340,2020 2170.71,2189.29 2170.71,2325.71 2278.02,2433.02 2278.02,2690 2195,2690 800,2690 780,2710 780,2785 765,2800 725,2800 215,2800 215,2595 0,2595 0,2505 215,2505 215,1995 -5.38,1995 -5.38,1900.22 215,1900.22 215,1395 -5.38,1395 -5.38,1305 215,1305 215,795 0,795 0,700 215,700
GND on Layer 1 - Top Layer "Layer 1 - Top Layer-No Net 6" (solid, pour order 108): 2200,-61.65 2241.85,-61.65 2243,-60.5 2243,45 2225,45 2200,20
GND on Layer 1 - Top Layer "Layer 1 - Top Layer-No Net" (solid, pour order 106): 2000,225 1998.9,226.1 1685,226.1 1685,268 1685,294.94 1712.66,294.94 1739.6,268 2000.5,268
GND on Layer 1 - Top Layer "Layer 1 - Top Layer-No Net 3" (solid, pour order 94): 2925,3070 2882,3070 2882,2758.21 2925,2758.21
-18V on Layer 1 - Top Layer "Layer 1 - Top Layer-No Net 4" (solid, pour order 58): 2910,3216.73 2910,3379.37 2819,3379.37 2819,3305.37 2819,3216.73
GND on Layer 1 - Top Layer "Layer 1 - Top Layer-No Net 1" (solid, pour order 30): 1025.69,3822.89 927.78,3822.89 902.54,3797.66 902.54,3684.74 851.15,3633.34 851.15,3542.89 1000.69,3542.89 1025.69,3567.89
+24VDC_IN on Layer 1 - Top Layer "Layer 4 - Bottom Layer-No Net" (solid, pour order 28): 380,3511.45 380,3780 410,3810 485,3810 490,3810 520,3780 520,3511.45
GND on Layer 1 - Top Layer "Layer 1 - Top Layer-No Net 5" (solid, pour order 68): 2340,3205 2340,3255 2290,3255 2248.78,3213.78 2248.78,3175 2248.78,2843.19 2251.97,2840 2275,2840 2275,3185 2295,3205
GND on Layer 1 - Top Layer "Layer 1 - Top Layer-No Net 2" (solid, pour order 90): 3283.12,3287.28 3283.12,3182.28 3268.12,3167.28 3060,3167.28 3060,3217.28 3203.12,3217.28 3203.12,3277.28 3213.12,3287.28
-0.2V on Layer 1 - Top Layer "Layer 1 - Top Layer-No Net 7" (solid, pour order 118): 2229.25,787.23 2462.25,787.23 2462.25,696.57 2229.59,696.57
-18.5V on Layer 4 - Bottom Layer "Layer 1 - Top Layer-No Net 8" (solid, pour order 120): 2780,3256 2780,3330 2700.12,3330 2700,3370 2549.38,3370 2465,3285.62 2465,3230 2465,3150 2625,3149.71 2625,3185 2570,3185 2570,3245 2580,3255
PRE on Layer 4 - Bottom Layer "Layer 4 - Bottom Layer-No Net 3" (solid, pour order 114): 2480,3715 2480,3680 2360.67,3680 2345.67,3665 2340.67,3660 2280,3660 2280,3745 2335,3745 2365,3715
GND on Layer 4 - Bottom Layer "Layer 4 - Bottom Layer-No Net 2" (solid, pour order 112): 2915,3600 3005,3600 3005,3575 2990,3560 2980,3560 2936.25,3560 2915,3581.25
3.3V on Layer 4 - Bottom Layer "Layer 4 - Bottom Layer-No Net 27" (solid, pour order 104): 1950,270 2060,270 2080,250 2185,250 2185,125 2155,95 2020,95 2020,115 2020,145 2015,150 1980,150 1980,170 1970,180 1950,180 1950,235
3.8V on Layer 4 - Bottom Layer "Layer 4 - Bottom Layer-No Net 26" (solid, pour order 102): 1555,-55 1730,-55 1775,-10 1775,100 1775,150 1820,150 1850,180 1850,190 1860,200 1863.54,203.54 1863.54,280 1726.06,280 1725.63,279.57 1710,263.94 1710,100 1710,96 1639,25 1555,25
GND on Layer 4 - Bottom Layer "Layer 4 - Bottom Layer-No Net 25" (solid, pour order 100): 1870,40 1940,40 1965,40 1965,170 1940,170 1940,345 1950,355 2056.26,355 2065,355 2090,330 2185,330 2185,455 1685,455 1685,350.43 1804.37,350.43 1804.37,310.63 1815,300 1853.7,300 1870,300 1870,165 1847.21,165 1847.21,40
NetCff3_1 on Layer 4 - Bottom Layer "Layer 4 - Bottom Layer-No Net 24" (solid, pour order 98): 1305,205 1305,155 1301.46,155 1265,118.54 1265,65.12 1314.88,65.12 1325,55 1330,50 1330,-45 1460,-45 1530,-45 1530,25 1460,25 1460,110 1470,120 1470,170 1470,185 1450,205
+24VDC on Layer 4 - Bottom Layer "Layer 4 - Bottom Layer-No Net 23" (solid, pour order 96): 1305,665.12 1305,470 1395,470 1415,490 1421.3,496.3 1510,496.3 1510,580 1425,665
+18V on Layer 4 - Bottom Layer "Layer 4 - Bottom Layer-No Net 13" (solid, pour order 64): 2005,3035 2005,3075 2055,3125 2450,3125 2450,2955 2035,2955 2035,2970 2075,2970 2075,3000 2040,3000 2035,3005
GND on Layer 4 - Bottom Layer "Layer 4 - Bottom Layer-No Net 12" (solid, pour order 62): 1925,2900 1995,2900 2020,2900 2020,3020 1995,3020 1995,3080 1995,3090 2020,3115 2020,3200 2255,3200 2255,3370 2065,3370 1940,3245 1842.6,3245 1842.6,3200 1985,3200 1985,3130 1955,3100 1925,3100 1925,3020 1902.21,3020 1902.21,2900
NetC9_1 on Layer 4 - Bottom Layer "Layer 4 - Bottom Layer-No Net 10" (solid, pour order 60): 1660,2945 1785,3070 1790,3070 1825,3070 1842.5,3087.5 1842.5,3125 1895,3125 1915,3145 1915,3182.5 1970,3182.5 1970,3140 1955,3125 1930,3125 1915,3110 1915,3070 1915,3035 1895,3035 1885,3025 1885,3005 1820,3005 1780,2965 1765,2950 1735,2920 1735,2865 1660,2865
+24VDC on Layer 4 - Bottom Layer "Layer 4 - Bottom Layer-No Net 14" (solid, pour order 70): 780,3480 910,3480 910,3380 995,3295 1000,3290 1000,3230 815,3230 810,3235 780,3265 780,3425
NetC34_2 on Layer 4 - Bottom Layer "Layer 4 - Bottom Layer-No Net 15" (solid, pour order 72): 2895,3470 2770,3345 2365,3345 2365,3501.6 2361.6,3505 2366.6,3500 2515,3500 2515,3810 2631.6,3810 2635,3761.4 2590,3761.4 2590,3500 2631.6,3500 2666.6,3465 2674.95,3473.35 2784.72,3473.35 2795.68,3484.32 2795.68,3585 2895,3585
+24VDC on Layer 4 - Bottom Layer "Layer 4 - Bottom Layer-No Net 17" (solid, pour order 76): 1445,3790 1445,3675 1475,3645 1475,3485 1710,3485 1710,3715 1635,3790
+24VDC on Layer 4 - Bottom Layer "Layer 4 - Bottom Layer-No Net 18" (solid, pour order 78): 3010,3665 2744.55,3665 2744.55,3759.55 2755,3770 2765,3780 2920,3780 2945,3780 3010,3715
+24VDC on Layer 4 - Bottom Layer "Layer 4 - Bottom Layer-No Net 19" (solid, pour order 80): 3484.76,3785 3484.76,3570 3704.76,3570 3709.76,3565 3709.76,3735.24 3660,3785
NetCff2_1 on Layer 4 - Bottom Layer "Layer 4 - Bottom Layer-No Net 20" (solid, pour order 82): 3499.76,3085 3484.76,3100 3484.76,3305 3654.76,3305 3654.76,3250 3689.76,3250 3699.76,3240 3699.76,3085
GND on Layer 4 - Bottom Layer "Layer 4 - Bottom Layer-No Net 11" (solid, pour order 84): 3060,2930 3060,2865 3060,2840 3190,2840 3190,2865 3360,2865 3365,2860 3370,2855 3370,2700 3370,2670 3410,2630 3518.54,2630 3518.54,3011.46 3430,3100 3370,3100 3370,2983.68 3315,2983.68 3315,2930 3190,2930 3190,2960 3060,2960
5V on Layer 4 - Bottom Layer "Layer 4 - Bottom Layer-No Net 21" (solid, pour order 86): 3200,2855 3290,2855 3290,2770 3325,2735 3325,2635 3190,2635 3115,2635 3115,2825 3135,2825 3135,2785 3165,2785 3165,2825 3195,2855
5.5V on Layer 4 - Bottom Layer "Layer 4 - Bottom Layer-No Net 22" (solid, pour order 88): 3165,3010 3165,2980 3205,2940 3295,2940 3295,3072.4 3292.4,3075 3165,3075
GND on Layer 4 - Bottom Layer "Layer 4 - Bottom Layer-No Net 4" (solid, pour order 116): 2322.25,617.23 2457.25,617.23 2462.25,617.23 2492.25,647.23 2505.51,660.49 2505.51,705.78 2570.8,705.78 2576.6,705.78 2576.6,607.88 2607.25,577.23 2607.25,534.2 2322.25,534.2
GND on Layer 4 - Bottom Layer "Layer 4 - Bottom Layer-No Net 1" (solid, pour order 122): 2101,610 2280,610 2280,481.7 2274.75,476.45 2273.3,475 2190,475 2180.76,475 2101,554.76

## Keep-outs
Keep-Out Layer:
  text ".Layer_Name" at 577,-1158.49 h60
